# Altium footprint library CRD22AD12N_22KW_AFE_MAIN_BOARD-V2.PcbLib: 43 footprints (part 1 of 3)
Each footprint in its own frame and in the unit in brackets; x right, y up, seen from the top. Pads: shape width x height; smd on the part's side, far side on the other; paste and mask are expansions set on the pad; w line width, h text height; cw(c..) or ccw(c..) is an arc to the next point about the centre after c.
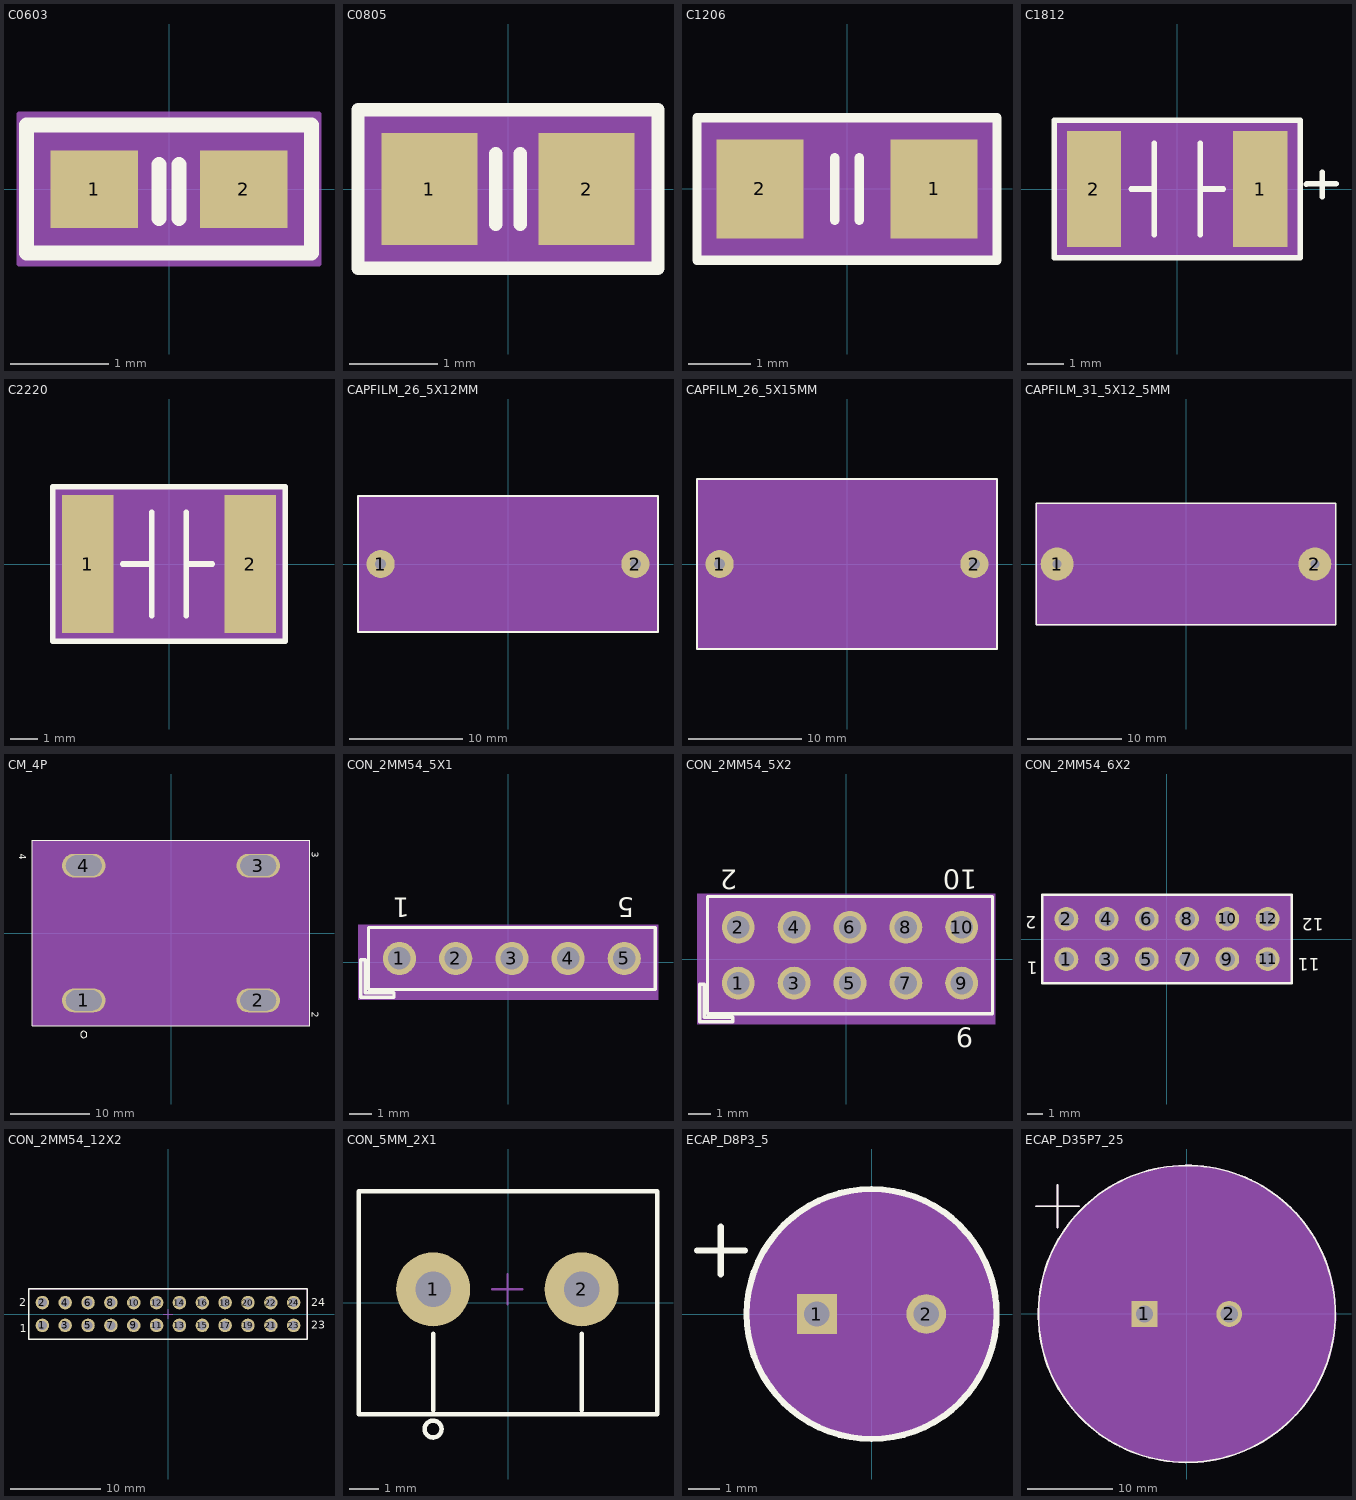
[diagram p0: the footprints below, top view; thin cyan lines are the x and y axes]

## C0603 [mil] "C0603"
pads (2):
  rect 35x31 smd: 1(-29.92,0) 2(29.92,0)
Top Overlay:
  lines w6: -3.94,-11.81 -3.94,9.84 ; 3.94,-11.81 3.94,9.84 ; -57.09,-25.59 57.09,-25.59 57.09,25.59 -57.09,25.59 -57.09,-25.59
  text ".Designator" at 52.5,71.85 h35
Top Courtyard:
  dashed: -60,-30 -60,30 60,30 60,-30
Top Component Center:
  lines w3: -20,0 20,0 ; 0,-20 0,20
Top Assembly:
  lines w2: -60,-30 -60,30 60,30 60,-30 -60,-30
  text "1uF" at -37.2,-16 h31
  text "#TOL" at -49.6,-16 h31
  text "HAMP" at -49.6,-16 h31
Mechanical 24:
  text "2" at 25.92,0 h10
  text "1" at -33.92,0 h10
3D body: height 150, standoff 0, extent -31.5,-15.75 31.5,15.75

## C0805 [mil] "C0805"
pads (2):
  rect 43x50 smd: 1(-35.04,0) 2(35.04,0)
Top Overlay:
  lines w6: -5.51,-15.75 -5.51,15.75 ; 5.51,-15.75 5.51,15.75 ; -66.93,-35.43 -66.93,35.43 66.93,35.43 66.93,-35.43 -66.93,-35.43
  text ".Designator" at 115,-55 h35
Top Courtyard:
  dashed: -65,-35 -65,35 65,35 65,-35
Top Component Center:
  lines w3: -20,0 20,0 ; 0,-20 0,20
Top Assembly:
  lines w2: -65,-35 -65,35 65,35 65,-35 -65,-35
  text "HAMP" at -55,-11.4 h31
  text "#TOL" at -55,-11.4 h31
  text "2.2u" at -55,-11.4 h31
Mechanical 24:
  text "2" at 35.04,4 h10
  text "1" at -35.04,4 h10
3D body: height 150, standoff 0, extent -39.37,-24.61 39.37,24.61

## C1206 [mil] "C1206"
pads (2):
  rect 55x63 smd: 1(55.12,0) 2(-55.12,0)
Top Overlay:
  lines w6: -7.87,-19.69 -7.87,19.69 ; 7.87,-19.69 7.87,19.69 ; -95,-45 -95,45 95,45 95,-45 -95,-45
  text ".Designator" at 110,-60 h35
Top Courtyard:
  dashed: 95,45 95,-45 -95,-45 -95,45
Top 3D Body:
  region: 62.99,31.5 62.99,-31.5 -62.99,-31.5 -62.99,31.5
Top Component Center:
  lines w3: -20,0 20,0 ; 0,-20 0,20
Top Assembly:
  lines w2: -95,-45 -95,45 95,45 95,-45 -95,-45
  text "2u2" at 57.8,16 h31
  text "#TOL" at 45.4,16 h31
  text "HAMP" at 45.4,16 h31
Mechanical 24:
  text "1" at 51.12,0 h10
  text "2" at -59.12,0 h10
3D body: height 25, standoff 0, extent -62.99,-31.5 62.99,31.5

## C1812 [mil] "C1812"
pads (2):
  rect 59x126 smd: 1(90.55,0) 2(-90.55,0)
Top Overlay:
  lines w6: -50,0 -25,0 ; -25,-50 -25,50 ; 25,-50 25,50 ; 25,0 50,0 ; 140.78,5.17 141.18,5.57 172.98,5.57 ; 157.83,-8.38 157.83,18.32 ; -133.86,-74.8 -133.86,74.8 133.86,74.8 133.86,-74.8 -133.86,-74.8
  text ".Designator" at 125,-100 h35
Top Courtyard:
  dashed: 135,75 135,-75 -135,-75 -135,75
Top 3D Body:
  region: 88.58,62.99 88.58,-62.99 -88.58,-62.99 -88.58,62.99
Top Component Center:
  lines w3: -20,0 20,0 ; 0,-20 0,20
Top Assembly:
  lines w2: -130,-70 -130,70 130,70 130,-70 -130,-70
  text "220p" at 55.4,16 h31
  text "#TOL" at 55.4,16 h31
  text "HAMP" at 55.4,16 h31
Mechanical 24:
  text "2" at -94.55,0 h10
  text "1" at 86.55,0 h10
3D body: height 150, standoff 0, extent -88.58,-62.99 88.58,62.99

## C2220 [mm] "C2220"
pads (2):
  rect 1.905x5.08 smd: 1(-3,0) 2(3,0)
Top Overlay:
  lines w0.2: -4.3,-2.85 -4.3,2.85 4.3,2.85 4.3,-2.85 -4.3,-2.85
  lines w0.203: -1.7,0 -0.635,0 ; -0.635,-1.905 -0.635,1.905 ; 0.635,-1.905 0.635,1.905 ; 0.635,0 1.6,0
  text ".Designator" at -3.175,-4.064 h0.89
Top Courtyard:
  dashed: -4.318,-2.794 -4.318,2.794 4.318,2.794 4.318,-2.794
Top 3D Body:
  region: -2.8,-2.5 -2.8,2.5 2.8,2.5 2.8,-2.5
Top Component Center:
  lines w0.076: -0.508,0 0.508,0 ; 0,-0.508 0,0.508
Top Assembly:
  lines w0.025: -4.191,-2.794 -4.191,2.794 4.191,2.794 4.191,-2.794 -4.191,-2.794
  text "HAMP" at -2.286,-0.579 h1.22
  text "#TOL" at -2.286,-0.579 h1.22
  text "0u1" at -2.286,-0.091 h1.22
Mechanical 24:
  text "1" at -3,-1.626 h4.06
  text "2" at 3,-1.626 h4.06
3D body: height 1.27, standoff 0, extent -2.8,-2.5 2.8,2.5

## CAPFILM_26_5X12MM [mil] "CAPFILM_26_5X12MM"
pads (2):
  round 98 hole 39: 1(-442.91,0) 2(442.91,0)
Top Overlay:
  lines w6: -521.65,-236.22 521.65,-236.22 521.65,236.22 -521.65,236.22 -521.65,-236.22
  text ".Designator" at 5,-260 h35
Top Courtyard:
  dashed: -521.65,-236.22 521.65,-236.22 521.65,236.22 -521.65,236.22
Top 3D Body:
  region: -521.65,-236.22 521.65,-236.22 521.65,236.22 -521.65,236.22
Top Component Center:
  lines w3: -20,0 20,0 ; 0,-20 0,20
Top Assembly:
  lines w2: -521.65,-236.22 521.65,-236.22 521.65,236.22 -521.65,236.22 -521.65,-236.22
  text "HAMP" at 49.6,-16 h31
  text "#TOL" at 49.6,-16 h31
  text "2.2uF" at 62,-16 h31
Mechanical 24:
  text "1" at -438.91,0 h10
  text "2" at 446.91,0 h10
3D body: height 150, standoff 0, extent -521.65,-236.22 521.65,236.22

## CAPFILM_26_5X15MM [mil] "CAPFILM_26_5X15MM"
pads (2):
  round 98 hole 39: 1(-442.91,0) 2(442.91,0)
Top Overlay:
  lines w6: -521.65,-295.28 -521.65,295.28 521.65,295.28 521.65,-295.28 -521.65,-295.28
  text ".Designator" at 575,-50 h35
Top Courtyard:
  dashed: -521.65,-295.28 521.65,-295.28 521.65,295.28 -521.65,295.28
Top 3D Body:
  region: -521.65,-295.28 521.65,-295.28 521.65,295.28 -521.65,295.28
Top Component Center:
  lines w3: -20,0 20,0 ; 0,-20 0,20
Top Assembly:
  lines w2: -521.65,-295.28 -521.65,295.28 521.65,295.28 521.65,-295.28 -521.65,-295.28
  text "3.3uF" at 0,-78 h31
  text "#TOL" at 0,-65.6 h31
  text "HAMP" at 0,-65.6 h31
Mechanical 24:
  text "1" at -442.91,-4 h10
  text "2" at 442.91,-4 h10
3D body: height 150, standoff 0, extent -521.65,-295.28 521.65,295.28

## CAPFILM_31_5X12_5MM [mil] "CAPFILM_31_5X12_5MM"
pads (2):
  round 138 hole 39: 1(-541.34,0) 2(541.34,0)
Top Overlay:
  lines w6: -629.92,-255.91 629.92,-255.91 629.92,255.91 -629.92,255.91 -629.92,-255.91
  text ".Designator" at -195,275.68 h35
Top Courtyard:
  dashed: -629.92,-255.91 629.92,-255.91 629.92,255.91 -629.92,255.91
Top 3D Body:
  region: -629.92,-255.91 629.92,-255.91 629.92,255.91 -629.92,255.91
Top Component Center:
  lines w3: -20,0 20,0 ; 0,-20 0,20
Top Assembly:
  lines w2: -629.92,-255.91 629.92,-255.91 629.92,255.91 -629.92,255.91 -629.92,-255.91
  text "2.2u" at 0,33.6 h31
  text "#TOL" at 0,33.6 h31
  text "HAMP" at 0,33.6 h31
Mechanical 24:
  text "2" at 541.34,4 h10
  text "1" at -541.34,4 h10
3D body: height 150, standoff 0, extent -629.92,-255.91 629.92,255.91

## CM_4P [mm] "CM_4P"
pads (4):
  oval 5.5x3 hole 4.5 slot 2.6 at 90 deg: 1(-11,-8.5) 2(11,-8.5) 3(11,8.5) 4(-11,8.5)
Top Overlay:
  circle w0.152: c-11,-12.8 r0.4
  lines w0.152: -17.5,-11.7 17.5,-11.7 17.5,11.7 -17.5,11.7 -17.5,-11.7
  text ".Designator" at 18.288,1.905 h0.89
  text "4" at -19.177,10.033 h0.89
  text "3" at 17.78,10.287 h0.89
  text "2" at 17.78,-9.906 h0.89
Top 3D Body:
  region: -17.5,11.7 -17.5,-11.7 17.5,-11.7 17.5,11.7
Top Component Center:
  lines w0.076: -0.508,0 0.508,0 ; 0,-0.508 0,0.508
Top Assembly:
  text "HAMP" at 0,0.853 h0.79
  text "#TOL" at 0,0.853 h0.79
  text "6Ts" at 0,0.538 h0.79
Mechanical 24:
  text "4" at -11,8.602 h0.25
  text "3" at 11,8.602 h0.25
  text "1" at -11,-8.399 h0.25
  text "2" at 11,-8.399 h0.25
3D body: height 3.81, standoff 0, extent -17.5,-11.7 17.5,11.7

## CON_2MM54_5X1 [mil] "CON_2MM54_5X1"
pads (5):
  round 59 hole 40: 1(-193.11,6.89) 2(-93.11,6.89) 3(6.89,6.89) 4(106.89,6.89) 5(206.89,6.89)
Top Overlay:
  lines w6: -262.01,-62.01 -262.01,4.92 -254.13,4.92 -254.13,-54.13 -202.95,-54.13 -202.95,-62.01 -262.01,-62.01 ; -248.23,-48.23 -248.23,62.01 262.01,62.01 262.01,-48.23 -248.23,-48.23
  text ".Designator" at 30,-81.44 h35
  text "1" at -174.92,115.02 h35
  text "5" at 225.08,115.02 h35
Top 3D Body:
  region: -266.93,-66.93 266.93,-66.93 266.93,66.93 -266.93,66.93
Top Component Center:
  lines w3: -13.11,6.89 26.89,6.89 ; 6.89,-13.11 6.89,26.89
Top Assembly:
  lines w2: -262.01,-62.01 -262.01,4.92 -254.13,4.92 -254.13,-54.13 -202.95,-54.13 -202.95,-62.01 -262.01,-62.01 ; -248.23,-48.23 -248.23,62.01 262.01,62.01 262.01,-48.23 -248.23,-48.23
  text "HAMP" at 56.49,-9.11 h31
  text "#TOL" at 56.49,-9.11 h31
  text "CON5" at 56.49,-9.11 h31
Mechanical 24:
  text "5" at 210.89,6.89 h10
  text "4" at 110.89,6.89 h10
  text "2" at -89.11,6.89 h10
  text "1" at -189.11,6.89 h10
  text "3" at 10.89,6.89 h10
3D body: height 150, standoff 0, extent -266.93,-66.93 266.93,66.93

## CON_2MM54_5X2 [mil] "CON_2MM54_5X2"
pads (10):
  round 59 hole 40: 1(-193.11,-43.11) 2(-193.11,56.89) 3(-93.11,-43.11) 4(-93.11,56.89) 5(6.89,-43.11) 6(6.89,56.89) 7(106.89,-43.11) 8(106.89,56.89) 9(206.89,-43.11) 10(206.89,56.89)
Top Overlay:
  lines w6: -262.01,-112.01 -262.01,-45.08 -254.13,-45.08 -254.13,-104.13 -202.95,-104.13 -202.95,-112.01 -262.01,-112.01 ; -248.23,-98.23 -248.23,112.01 262.01,112.01 262.01,-98.23 -248.23,-98.23
  text ".Designator" at 69.1,-131.44 h35
  text "2" at -194.92,160.02 h35
  text "10" at 235.08,160.02 h35
  text "9" at 227.44,-123.31 h35
Top 3D Body:
  region: -266.93,-116.93 266.93,-116.93 266.93,116.93 -266.93,116.93
Top Component Center:
  lines w3: -13.11,6.89 26.89,6.89 ; 6.89,-13.11 6.89,26.89
Top Assembly:
  lines w2: -262.01,-112.01 -262.01,-45.08 -254.13,-45.08 -254.13,-104.13 -202.95,-104.13 -202.95,-112.01 -262.01,-112.01 ; -248.23,-98.23 -248.23,112.01 262.01,112.01 262.01,-98.23 -248.23,-98.23
  text "HAMP" at 56.49,-9.11 h31
  text "#TOL" at 56.49,-9.11 h31
  text "CON10A" at 81.29,-9.11 h31
Mechanical 24:
  text "6" at 10.89,56.89 h10
  text "5" at 10.89,-43.11 h10
  text "10" at 214.89,56.89 h10
  text "1" at -189.11,-43.11 h10
  text "9" at 210.89,-43.11 h10
  text "2" at -189.11,56.89 h10
  text "8" at 110.89,56.89 h10
  text "7" at 110.89,-43.11 h10
  text "4" at -89.11,56.89 h10
  text "3" at -89.11,-43.11 h10
3D body: height 150, standoff 0, extent -266.93,-116.93 266.93,116.93

## CON_2MM54_6X2 [mil] "CON_2MM54_6X2"
pads (12):
  round 59 hole 39: 1(-250,-50) 2(-250,50) 3(-150,-50) 4(-150,50) 5(-50,-50) 6(-50,50) 7(50,-50) 8(50,50) 9(150,-50) 10(150,50) 11(250,-50) 12(250,50)
Top Overlay:
  lines w6: -310,-110 310,-110 310,110 -310,110 -310,-110
  text ".Designator" at 155,-133.33 h35
  text "11" at 379,-48 h31
  text "1" at -321,-56 h31
  text "2" at -325.5,57 h31
  text "12" at 389,52 h31
Top Courtyard:
  dashed: -310,-110 310,-110 310,110 -310,110
Top 3D Body:
  region: -310,-110 310,-110 310,110 -310,110
Top Component Center:
  lines w3: -20,0 20,0 ; 0,-20 0,20
Top Assembly:
  lines w2: -310,-110 310,-110 310,110 -310,110 -310,-110
  text "HAMP" at 49.6,-16 h31
  text "#TOL" at 49.6,-16 h31
  text "CON12A" at 74.4,-16 h31
Mechanical 24:
  text "5" at -46,-50 h10
  text "1" at -246,-50 h10
  text "3" at -146,-50 h10
  text "7" at 54,-50 h10
  text "11" at 258,-50 h10
  text "4" at -146,50 h10
  text "2" at -246,50 h10
  text "12" at 258,50 h10
  text "6" at -46,50 h10
  text "9" at 154,-50 h10
  text "8" at 54,50 h10
  text "10" at 158,50 h10
3D body: height 150, standoff 0, extent -310,-110 310,110

## CON_2MM54_12X2 [mil] "CON_2MM54_12X2"
pads (24):
  round 59 hole 39: 1(-550,-50) 2(-550,50) 3(-450,-50) 4(-450,50) 5(-350,-50) 6(-350,50) 7(-250,-50) 8(-250,50) 9(-150,-50) 10(-150,50) 11(-50,-50) 12(-50,50) 13(50,-50) 14(50,50) 15(150,-50) 16(150,50) 17(250,-50) 18(250,50) 19(350,-50) 20(350,50) 21(450,-50) 22(450,50) 23(550,-50) 24(550,50)
Top Overlay:
  lines w6: -610,-110 610,-110 610,110 -610,110 -610,-110
  text ".Designator" at -80,138.33 h35
  text "24" at 626,35 h35
  text "2" at -652.28,33.78 h35
  text "1" at -650,-80 h35
  text "23" at 626,-65 h35
Top Courtyard:
  lines w1: -610,-110 610,-110 610,110 -610,110 -610,-110
Top 3D Body:
  lines w1: -610,-110 610,-110 610,110 -610,110 -610,-110
Top Component Center:
  lines w3: -20,0 20,0 ; 0,-20 0,20
Top Assembly:
  lines w2: -610,-110 -610,110 610,110 610,-110 -610,-110
  text "HAMP" at -49.6,-16 h31
  text "#TOL" at -49.6,-16 h31
  text "CON24A" at -74.4,-16 h31
Mechanical 24:
  text "23" at 542,-50 h10
  text "8" at -254,50 h10
  text "10" at -158,50 h10
  text "12" at -58,50 h10
  text "19" at 342,-50 h10
  text "17" at 242,-50 h10
  text "16" at 142,50 h10
  text "14" at 42,50 h10
  text "15" at 142,-50 h10
  text "6" at -354,50 h10
  text "5" at -354,-50 h10
  text "2" at -554,50 h10
  text "9" at -154,-50 h10
  text "11" at -58,-50 h10
  text "3" at -454,-50 h10
  text "7" at -254,-50 h10
  text "4" at -454,50 h10
  text "1" at -554,-50 h10
  text "20" at 342,50 h10
  text "22" at 442,50 h10
  text "24" at 542,50 h10
  text "18" at 242,50 h10
  text "21" at 442,-50 h10
  text "13" at 42,-50 h10

## CON_5MM_2X1 [mil] "CON_5MM_2X1"
pads (2):
  round 98 hole 47: 1(-99.22,17.71) 2(97.64,17.71)
Top Overlay:
  circle w6: c-99.22,-167.29 r11.19
  lines w6: -99.22,-142.29 -99.22,-41.34 ; 97.64,-142.29 97.64,-41.34 ; -197.64,-147.64 -197.64,147.63 197.64,147.63 197.64,-147.64 -197.64,-147.64
  text ".Designator" at -280,-36.67 h35
Top Courtyard:
  lines w1: -198.64,-148.64 198.64,-148.64 198.64,148.63 -198.64,148.63 -198.64,-148.64
Top 3D Body:
  lines w1: -198.64,-148.64 198.64,-148.64 198.64,148.63 -198.64,148.63 -198.64,-148.64
Top Component Center:
  lines w3: -20.79,17.71 19.21,17.71 ; -0.79,-2.29 -0.79,37.71
Top Assembly:
  lines w2: -99.22,-142.29 -99.22,-41.34 ; 97.64,-142.29 97.64,-41.34 ; -197.64,-147.64 -197.64,147.63 197.64,147.63 197.64,-147.64 -197.64,-147.64
  text "HAMP" at -50.39,1.71 h31
  text "#TOL" at -50.39,1.71 h31
  text "CON2" at -50.39,1.71 h31
Mechanical 24:
  text "2" at 93.64,17.71 h10
  text "1" at -103.22,17.71 h10

## ECAP_D8P3_5 [mil] "ECAP_D8P3_5"
pads (2):
  rect 50x50 hole 32: 1(-68.9,0)
  round 50 hole 32: 2(68.9,0)
Top Overlay:
  circle w7.87: c0,0 r157.48
  lines w8: -220,80 -160,80 ; -190,50 -190,110
  text ".Designator" at -310,-11.67 h35
Top Courtyard:
  dashed: 157.97,0 156.02,24.71 150.24,48.81 140.75,71.72 127.8,92.85 111.7,111.7 92.85,127.8 71.72,140.75 48.81,150.24 24.71,156.02 0,157.97 -24.71,156.02 -48.81,150.24 -71.72,140.75 -78.77,136.43 -92.85,127.8 -111.7,111.7 -127.8,92.85 -140.75,71.72 -150.24,48.81 -156.02,24.71 -157.97,0 -156.02,-24.71 -150.24,-48.81 -140.75,-71.72 -127.8,-92.85 -111.7,-111.7 -92.85,-127.8 -78.77,-136.43 -71.72,-140.75 -48.81,-150.24 -24.71,-156.02 0,-157.97 24.71,-156.02 48.81,-150.24 71.72,-140.75 92.85,-127.8 111.7,-111.7 127.8,-92.85 140.75,-71.72 150.24,-48.81 156.02,-24.71
Top 3D Body:
  region: 157.97,0 156.02,24.71 150.24,48.81 140.75,71.72 127.8,92.85 111.7,111.7 92.85,127.8 71.72,140.75 48.81,150.24 24.71,156.02 0,157.97 -24.71,156.02 -48.81,150.24 -71.72,140.75 -78.77,136.43 -92.85,127.8 -111.7,111.7 -127.8,92.85 -140.75,71.72 -150.24,48.81 -156.02,24.71 -157.97,0 -156.02,-24.71 -150.24,-48.81 -140.75,-71.72 -127.8,-92.85 -111.7,-111.7 -92.85,-127.8 -78.77,-136.43 -71.72,-140.75 -48.81,-150.24 -24.71,-156.02 0,-157.97 24.71,-156.02 48.81,-150.24 71.72,-140.75 92.85,-127.8 111.7,-111.7 127.8,-92.85 140.75,-71.72 150.24,-48.81 156.02,-24.71
Top Component Center:
  lines w3: -20,0 20,0 ; 0,-20 0,20
Top Assembly:
  circle w1: c0,0 r157.48
  lines w1: 0,-157.48 ccw(c0,0) 0,157.48
  text "25V 220uF" at -111.6,-16 h31
  text "#TOL" at -49.6,-16 h31
  text "HAMP" at -49.6,-16 h31
Mechanical 24:
  text "2" at 58.9,0 h25
  text "1" at -78.9,0 h25
3D body: height 150, standoff 0, extent -157.97,-157.97 157.97,157.97

## ECAP_D35P7_25 [mil] "ECAP_D35P7_25"
pads (2):
  rect 120x120 / inner round 91 / far side rect 120x120 hole 79: 1(-196.85,0)
  round 120 / inner round 91 / far side round 120 hole 79: 2(196.85,0)
Top Overlay:
  circle w8: c0,0 r688.98
  lines w8: -700,500 -500,500 ; -600,400 -600,600
  text ".Designator" at 625,-450 h35
Top Courtyard:
  region: 3.32,-689.48 -19.23,-689.48 -64.25,-686.53 -108.97,-680.64 -153.21,-671.84 -196.79,-660.16 -239.5,-645.66 -281.18,-628.4 -321.63,-608.45 -360.7,-585.89 -398.21,-560.83 -434,-533.37 -467.91,-503.63 -499.81,-471.73 -529.55,-437.82 -557.01,-402.03 -582.07,-364.52 -604.63,-325.45 -624.58,-285 -641.84,-243.32 -656.34,-200.61 -668.02,-157.03 -676.82,-112.79 -682.71,-68.07 -685.66,-23.05 -685.66,-0.5 -685.66,22.05 -682.71,67.07 -676.82,111.79 -668.02,156.03 -656.34,199.61 -641.84,242.32 -624.58,284 -604.63,324.46 -582.07,363.52 -557.01,401.03 -529.55,436.82 -499.81,470.73 -467.91,502.63 -434,532.37 -398.21,559.83 -360.7,584.89 -321.63,607.45 -281.18,627.4 -239.5,644.66 -196.79,659.16 -153.21,670.84 -108.97,679.64 -64.25,685.53 -19.23,688.48 3.32,688.48 25.87,688.48 70.89,685.53 115.61,679.64 159.85,670.84 203.43,659.16 246.14,644.66 287.82,627.4 328.28,607.45 367.34,584.89 404.85,559.83 440.64,532.37 474.55,502.63 506.45,470.73 536.19,436.82 563.65,401.03 588.71,363.52 611.27,324.46 631.22,284 648.48,242.32 662.98,199.61 674.66,156.03 683.46,111.79 689.35,67.07 692.3,22.05 692.3,-0.5 692.3,-23.05 689.35,-68.07 683.46,-112.79 674.66,-157.03 662.98,-200.61 648.48,-243.32 631.22,-285 611.27,-325.45 588.71,-364.52 563.65,-402.03 536.19,-437.82 506.45,-471.73 474.55,-503.63 440.64,-533.37 404.85,-560.83 367.34,-585.89 328.28,-608.45 287.82,-628.4 246.14,-645.66 203.43,-660.16 159.85,-671.84 115.61,-680.64 70.89,-686.53 25.87,-689.48
Top Component Center:
  lines w3: -20,0 20,0 ; 0,-20 0,20
Top Assembly:
  circle w8: c0,0 r688.98
  lines w8: -700,500 -500,500 ; -600,400 -600,600
  text "HAMP" at 0,33.6 h31
  text "#TOL" at 0,33.6 h31
  text "500V 680uF" at 0,108 h31
Mechanical 24:
  text "2" at 196.85,10 h25
  text "1" at -196.85,10 h25
3D body: height 2500, standoff 0, extent -688.98,-688.98 688.98,688.98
